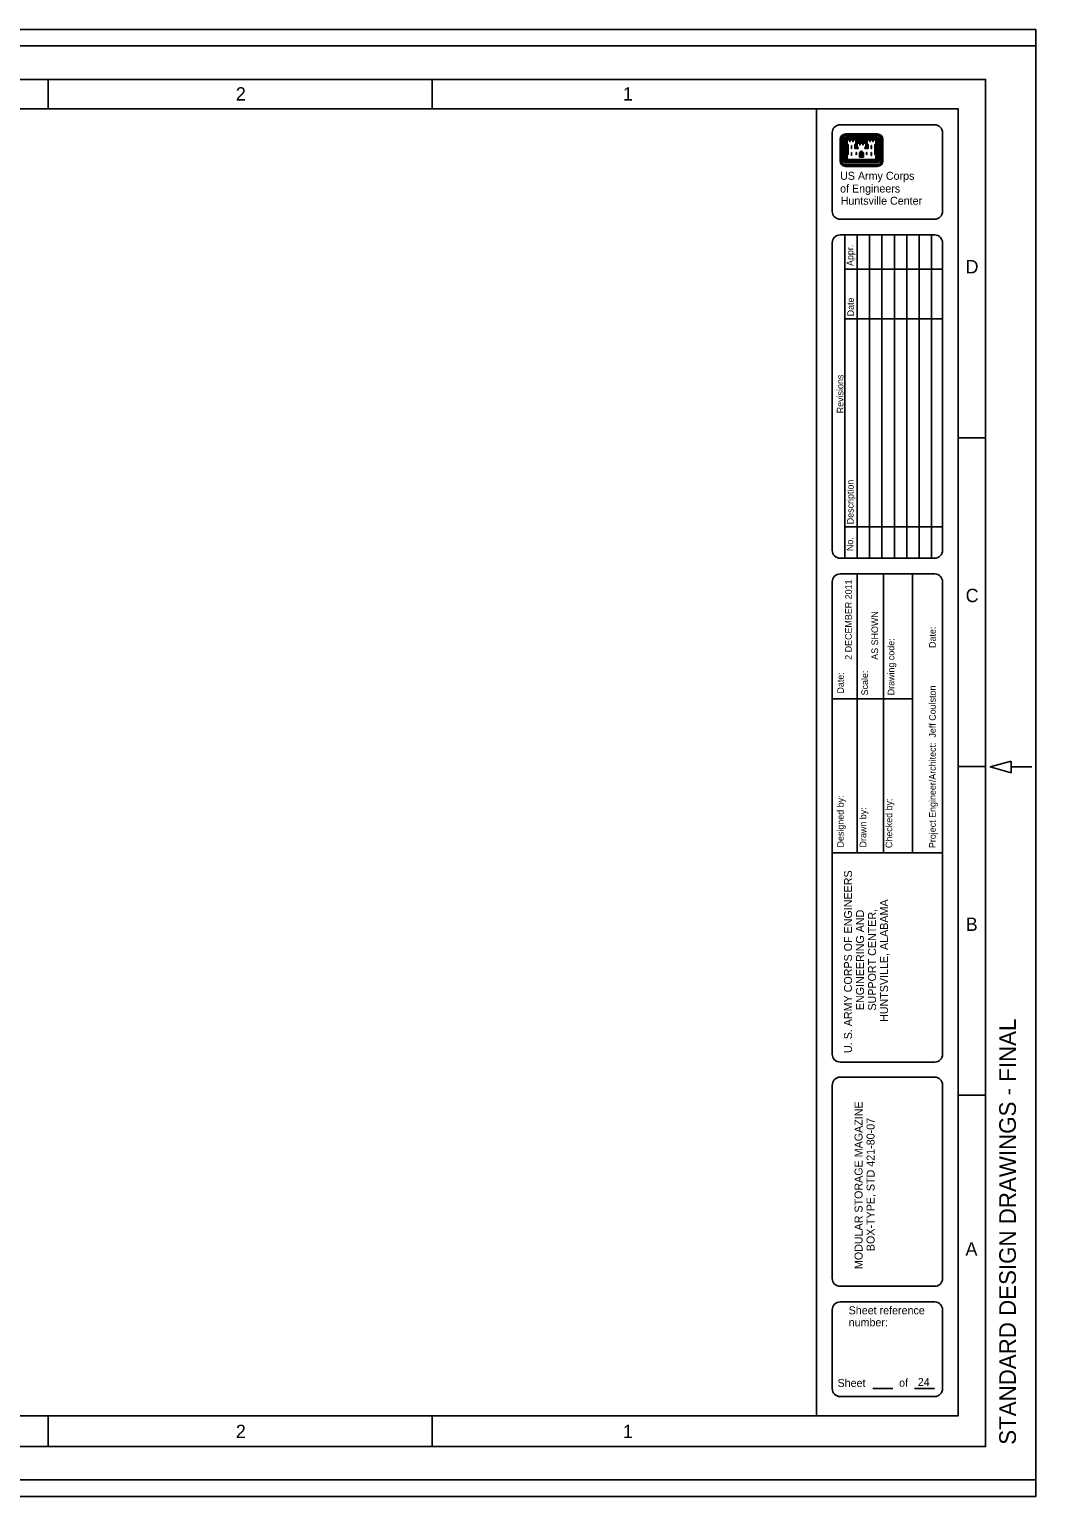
# Model space of a CAD drawing. Extents: x -0.04 to 2.79, y -0.02 to 1.81.
# Drawn here: x 1.534 to 2.792, y -0.021 to 1.813 of the extents above; entities that cross this region are included whole.
import ezdxf

# ---------------------------------------------------------------- set-up
doc = ezdxf.new("R2010")
doc.units = 0
for name, color, linetype in [('G-ANNO-NPLT', 7, 'Continuous'), ('G-ANNO-PLOT', 7, 'Continuous'), ('G-ANNO-TTLB', 7, 'Continuous')]:
    doc.layers.add(name, color=color, linetype=linetype)

msp = doc.modelspace()

# ---------------------------------------------------------------- linework, layer by layer
at = {"layer": 'G-ANNO-NPLT'}
msp.add_lwpolyline([(-0.0417, 1.8125), (2.7917, 1.8125), (2.7917, -0.0208), (-0.0417, -0.0208)], close=True, dxfattribs=at)
at = {"layer": 'G-ANNO-PLOT'}
for p, q in [((2.7917, 1.8125), (-0.0417, 1.8125)), ((2.7917, 1.8125), (2.7917, -0.0208)), ((2.7917, -0.0208), (-0.0417, -0.0208))]:
    msp.add_line(p, q, dxfattribs=at)
msp.add_lwpolyline([(0, 0), (2.7917, 0), (2.7917, 1.7917), (0, 1.7917)], close=True, dxfattribs=at)
at = {"layer": 'G-ANNO-TTLB'}
for p, q in [((1.5578, 1.7131), (1.5578, 1.75)), ((2.0378, 1.7131), (2.0378, 1.75)), ((2.5178, 0.0803), (2.5178, 1.7131)), ((2.5473, 1.6749), (2.5473, 1.6483)), ((2.5477, 1.6749), (2.5477, 1.6483)), ((2.5484, 1.6749), (2.5484, 1.6483)), ((2.5489, 1.6749), (2.5489, 1.6483)), ((2.5494, 1.6749), (2.5494, 1.6483)), ((2.5517, 1.6749), (2.5517, 1.6483)), ((2.5523, 1.6749), (2.5523, 1.6483)), ((2.5528, 1.6749), (2.5528, 1.6483)), ((2.5534, 1.6749), (2.5534, 1.6483)), ((2.554, 1.6749), (2.554, 1.6483)), ((2.5938, 1.6819), (2.5543, 1.6819)), ((2.5938, 1.6815), (2.5543, 1.6815)), ((2.5938, 1.6809), (2.5543, 1.6809)), ((2.5938, 1.6804), (2.5543, 1.6804)), ((2.5938, 1.6798), (2.5543, 1.6798)), ((2.5938, 1.6776), (2.5543, 1.6776)), ((2.5938, 1.677), (2.5543, 1.677)), ((2.5938, 1.6764), (2.5543, 1.6764)), ((2.5938, 1.6758), (2.5543, 1.6758)), ((2.5938, 1.6753), (2.5543, 1.6753)), ((2.5545, 1.6749), (2.5545, 1.6484)), ((2.5551, 1.6749), (2.5551, 1.649)), ((2.5555, 1.6692), (2.5555, 1.6556)), ((2.5561, 1.6686), (2.5561, 1.6563)), ((2.5679, 1.6747), (2.5801, 1.6747)), ((2.5679, 1.6742), (2.5801, 1.6742)), ((2.5679, 1.6737), (2.5801, 1.6737)), ((2.5679, 1.6731), (2.5801, 1.6731)), ((2.5679, 1.6725), (2.5801, 1.6725)), ((2.5679, 1.672), (2.5801, 1.672)), ((2.5679, 1.6714), (2.5801, 1.6714)), ((2.592, 1.6686), (2.592, 1.6563)), ((2.5925, 1.6692), (2.5925, 1.6557)), ((2.593, 1.6749), (2.593, 1.649)), ((2.5935, 1.6749), (2.5935, 1.6484)), ((2.5941, 1.6749), (2.5941, 1.6483)), ((2.5947, 1.6749), (2.5947, 1.6483)), ((2.5953, 1.6749), (2.5953, 1.6483)), ((2.5958, 1.6749), (2.5958, 1.6483)), ((2.5964, 1.6749), (2.5964, 1.6483)), ((2.5986, 1.6749), (2.5986, 1.6483)), ((2.5992, 1.6749), (2.5992, 1.6483)), ((2.5997, 1.6749), (2.5997, 1.6483)), ((2.6003, 1.6749), (2.6003, 1.6483)), ((2.6007, 1.6749), (2.6007, 1.6483)), ((2.5714, 1.6528), (2.5714, 1.6572)), ((2.5714, 1.6528), (2.5767, 1.6528)), ((2.5719, 1.6528), (2.5719, 1.6572)), ((2.5725, 1.6528), (2.5725, 1.6572)), ((2.5731, 1.6528), (2.5731, 1.6572)), ((2.5737, 1.6528), (2.5737, 1.6572)), ((2.5744, 1.6528), (2.5744, 1.6572)), ((2.575, 1.6528), (2.575, 1.6572)), ((2.5755, 1.6528), (2.5755, 1.6572)), ((2.5761, 1.6528), (2.5761, 1.6572)), ((2.5767, 1.6528), (2.5767, 1.6572)), ((2.5938, 1.6478), (2.5543, 1.6478)), ((2.5938, 1.6473), (2.5543, 1.6473)), ((2.5938, 1.6467), (2.5543, 1.6467)), ((2.5938, 1.6462), (2.5543, 1.6462)), ((2.5938, 1.6456), (2.5543, 1.6456)), ((2.5938, 1.6433), (2.5543, 1.6433)), ((2.5938, 1.6428), (2.5543, 1.6428)), ((2.5938, 1.6423), (2.5543, 1.6423)), ((2.5938, 1.6417), (2.5543, 1.6417)), ((2.5938, 1.6412), (2.5543, 1.6412)), ((2.5935, 1.6484), (2.5545, 1.6484)), ((2.593, 1.649), (2.5551, 1.649)), ((2.5532, 1.5557), (2.5532, 1.1517)), ((2.5686, 1.5557), (2.5686, 1.1517)), ((2.5842, 1.5557), (2.5842, 1.1517)), ((2.5996, 1.5557), (2.5996, 1.1517)), ((2.6151, 1.5557), (2.6151, 1.1517)), ((2.6306, 1.5557), (2.6306, 1.1517)), ((2.646, 1.5557), (2.646, 1.1517)), ((2.6615, 1.5557), (2.6615, 1.1517)), ((2.5532, 1.513), (2.6754, 1.513)), ((2.5532, 1.4507), (2.6754, 1.4507)), ((2.695, 1.3022), (2.7292, 1.3022)), ((2.5532, 1.1911), (2.6754, 1.1911)), ((2.5685, 1.1321), (2.5685, 0.976)), ((2.6014, 1.1321), (2.6014, 0.976)), ((2.6377, 1.1321), (2.6377, 0.7837)), ((2.6377, 0.976), (2.5376, 0.976)), ((2.5685, 0.976), (2.5685, 0.7837)), ((2.6014, 0.976), (2.6014, 0.7837)), ((2.695, 0.8914), (2.7292, 0.8914)), ((2.7609, 0.891), (2.787, 0.891)), ((2.6754, 0.7837), (2.5376, 0.7837)), ((2.5474, 0.5221), (2.6655, 0.5221)), ((2.695, 0.4806), (2.7292, 0.4806)), ((2.5883, 0.1141), (2.6134, 0.1141)), ((2.6403, 0.1141), (2.6654, 0.1141)), ((1.5578, 0.0418), (1.5578, 0.0803)), ((2.0378, 0.0418), (2.0378, 0.0803))]:
    msp.add_line(p, q, dxfattribs=at)
for points in [[(0.0833, 0.0417), (2.7292, 0.0417), (2.7292, 1.75), (0.2515, 1.75)], [(0.1166, 0.0803), (2.695, 0.0803), (2.695, 1.7131), (0.1166, 1.7131)], [(2.5474, 1.6934), (2.6655, 1.6934)], [(2.5376, 1.5851), (2.5376, 1.6835)], [(2.5555, 1.6749), (2.5555, 1.6698), (2.5567, 1.6686), (2.5567, 1.6563), (2.5555, 1.6551), (2.5555, 1.6494), (2.5926, 1.6494), (2.5926, 1.6551), (2.5914, 1.6563), (2.5914, 1.6686), (2.5926, 1.6698), (2.5926, 1.6749), (2.5877, 1.6749), (2.5839, 1.6749), (2.5804, 1.6749), (2.5804, 1.6698), (2.5817, 1.6686), (2.5817, 1.6642), (2.5789, 1.6642), (2.5789, 1.6646), (2.5801, 1.6657), (2.5801, 1.6708), (2.5752, 1.6708), (2.5714, 1.6708), (2.5679, 1.6708), (2.5679, 1.6657), (2.5691, 1.6646), (2.5691, 1.6642), (2.5664, 1.6642), (2.5664, 1.6686), (2.5676, 1.6698), (2.5676, 1.6749), (2.5626, 1.6749), (2.5589, 1.6749), (2.5555, 1.6749)], [(2.5561, 1.6743), (2.5561, 1.67), (2.5573, 1.6688), (2.5573, 1.656), (2.5561, 1.6549), (2.5561, 1.65), (2.592, 1.65), (2.592, 1.6549), (2.5909, 1.656), (2.5909, 1.6688), (2.592, 1.67), (2.592, 1.6743), (2.5886, 1.6743), (2.5886, 1.6723), (2.5883, 1.6723), (2.5883, 1.6743), (2.5848, 1.6743), (2.5848, 1.6723), (2.5845, 1.6723), (2.5845, 1.6743), (2.581, 1.6743), (2.581, 1.67), (2.5822, 1.6688), (2.5822, 1.6636), (2.5784, 1.6636), (2.5784, 1.6648), (2.5796, 1.6659), (2.5796, 1.6703), (2.5761, 1.6703), (2.5761, 1.6682), (2.5757, 1.6682), (2.5757, 1.6703), (2.5723, 1.6703), (2.5723, 1.6682), (2.5719, 1.6682), (2.5719, 1.6703), (2.5685, 1.6703), (2.5685, 1.6659), (2.5697, 1.6648), (2.5697, 1.6636), (2.5658, 1.6636), (2.5658, 1.6688), (2.5671, 1.67), (2.5671, 1.6743), (2.5636, 1.6743), (2.5636, 1.6723), (2.5633, 1.6723), (2.5633, 1.6743), (2.5598, 1.6743), (2.5598, 1.6723), (2.5595, 1.6723), (2.5595, 1.6743), (2.5561, 1.6743)], [(2.5673, 1.6687), (2.567, 1.6684), (2.567, 1.6647), (2.5682, 1.6647), (2.5674, 1.6655), (2.5674, 1.6688)], [(2.5807, 1.6687), (2.581, 1.6684), (2.581, 1.6647), (2.5799, 1.6647), (2.5807, 1.6655), (2.5807, 1.6688)], [(2.6754, 1.6835), (2.6754, 1.5851)], [(2.5614, 1.6674), (2.5614, 1.6636), (2.5617, 1.6636), (2.5617, 1.6674), (2.5614, 1.6674)], [(2.5614, 1.6587), (2.5614, 1.6549), (2.5617, 1.6549), (2.5617, 1.6587), (2.5614, 1.6587)], [(2.5673, 1.6587), (2.5673, 1.6561), (2.5677, 1.6561), (2.5677, 1.6587), (2.5673, 1.6587)], [(2.5807, 1.6587), (2.5807, 1.6561), (2.5804, 1.6561), (2.5804, 1.6587), (2.5807, 1.6587)], [(2.5867, 1.6674), (2.5867, 1.6636), (2.5863, 1.6636), (2.5863, 1.6674), (2.5867, 1.6674)], [(2.5867, 1.6587), (2.5867, 1.6549), (2.5863, 1.6549), (2.5863, 1.6587), (2.5867, 1.6587)], [(2.6655, 1.5753), (2.5474, 1.5753)], [(2.5376, 1.5458), (2.5376, 1.1615)], [(2.6655, 1.5557), (2.5474, 1.5557)], [(2.6754, 1.1615), (2.6754, 1.5458)], [(2.5474, 1.1517), (2.6655, 1.1517)], [(2.5376, 1.1223), (2.5376, 0.5321)], [(2.6655, 1.1321), (2.5474, 1.1321)], [(2.6754, 0.5319), (2.6754, 1.1223)], [(2.6655, 0.5033), (2.5474, 0.5033)], [(2.5376, 0.493), (2.5376, 0.2518)], [(2.6754, 0.2518), (2.6754, 0.4935)], [(2.5474, 0.242), (2.6655, 0.242)], [(2.5474, 0.2224), (2.6655, 0.2224)], [(2.5376, 0.1141), (2.5376, 0.2126)], [(2.6754, 0.2126), (2.6754, 0.1141)], [(2.6655, 0.1043), (2.5474, 0.1043)]]:
    msp.add_lwpolyline(points, dxfattribs=at)
msp.add_lwpolyline([(2.7609, 0.8983), (2.735, 0.891), (2.7609, 0.8837)], close=True, dxfattribs=at)
for centre, major_axis, start_param, end_param in [((2.5474, 1.6835), (-0.00984, 0), 4.712389, 6.283185), ((2.6655, 1.6835), (-0.00984, 0), 3.141593, 4.712389), ((2.5543, 1.6749), (-0.00696, 0), 4.712389, 6.283185), ((2.5543, 1.6749), (-0.00656, 0), 4.712389, 6.283185), ((2.5543, 1.6749), (-0.006, 0), 4.712389, 6.283185), ((2.5543, 1.6749), (-0.00543, 0), 4.712389, 6.283185), ((2.5543, 1.6749), (-0.00487, 0), 4.712389, 6.283185), ((2.5543, 1.6749), (-0.00261, 0), 4.712389, 6.283185), ((2.5543, 1.6749), (-0.00205, 0), 4.712389, 6.283185), ((2.5543, 1.6749), (-0.00148, 0), 4.712389, 6.283185), ((2.5543, 1.6749), (0.000919, 0), 1.570796, 3.141593), ((2.5543, 1.6749), (-0.000355, 0), 4.712389, 6.283185), ((2.5938, 1.6749), (-0.00696, 0), 3.141593, 4.712389), ((2.5938, 1.6749), (0.00656, 0), 0, 1.570796), ((2.5938, 1.6749), (0.006, 0), 0, 1.570796), ((2.5938, 1.6749), (0.00543, 0), 0, 1.570796), ((2.5938, 1.6749), (0.00487, 0), 0, 1.570796), ((2.5938, 1.6749), (-0.00261, 0), 3.141593, 4.712389), ((2.5938, 1.6749), (-0.00205, 0), 3.141593, 4.712389), ((2.5938, 1.6749), (-0.00148, 0), 3.141593, 4.712389), ((2.5938, 1.6749), (-0.000919, 0), 3.141593, 4.712389), ((2.5938, 1.6749), (-0.000355, 0), 3.141593, 4.712389), ((2.575, 1.6569), (0.00361, 0), 1.844255, 3.072783), ((2.575, 1.6569), (-0.00304, 0), 4.947481, 6.214375), ((2.575, 1.6569), (-0.00248, 0), 4.947481, 6.214375), ((2.575, 1.6569), (-0.00192, 0), 4.947481, 6.214375), ((2.5731, 1.6569), (0.00135, 0), 0.06881, 1.335704), ((2.5731, 1.6569), (0.00192, 0), 0.06881, 1.335704), ((2.5731, 1.6569), (-0.00248, 0), 3.210403, 4.477297), ((2.575, 1.6569), (-0.00135, 0), 4.947481, 6.214375), ((2.5731, 1.6569), (0.00304, 0), 0.06881, 1.335704), ((2.5731, 1.6569), (0.00361, 0), 0.06881, 1.298435), ((2.5543, 1.6482), (0.00696, 0), 3.141593, 4.712389), ((2.5543, 1.6482), (0.00656, 0), 3.141593, 4.712389), ((2.5543, 1.6482), (-0.006, 0), 0, 1.570796), ((2.5543, 1.6482), (0.00543, 0), 3.141593, 4.712389), ((2.5543, 1.6482), (0.00487, 0), 3.141593, 4.712389), ((2.5543, 1.6482), (0.00261, 0), 3.141593, 4.712389), ((2.5543, 1.6482), (0.00205, 0), 3.141593, 4.712389), ((2.5543, 1.6482), (0.00148, 0), 3.141593, 4.712389), ((2.5543, 1.6482), (0.000919, 0), 3.141593, 4.712389), ((2.5543, 1.6482), (0.000355, 0), 3.141593, 4.712389), ((2.5938, 1.6482), (0.00696, 0), 4.712389, 6.283185), ((2.5938, 1.6482), (0.00261, 0), 4.712389, 6.283185), ((2.5938, 1.6482), (0.00205, 0), 4.712389, 6.283185), ((2.5938, 1.6482), (0.00148, 0), 4.712389, 6.283185), ((2.5938, 1.6482), (0.000919, 0), 4.712389, 6.283185), ((2.5938, 1.6482), (0.000355, 0), 4.712389, 6.283185), ((2.5938, 1.6482), (0.00487, 0), 4.712389, 6.283185), ((2.5938, 1.6482), (0.00543, 0), 4.712389, 6.283185), ((2.5938, 1.6482), (0.006, 0), 4.712389, 6.283185), ((2.5938, 1.6482), (0.00656, 0), 4.712389, 6.283185), ((2.5474, 1.5851), (-0.00984, 0), 0, 1.570796), ((2.6655, 1.5851), (0.00984, 0), 4.712389, 6.283185), ((2.5474, 1.5458), (-0.00984, 0), 4.712389, 6.281588), ((2.6655, 1.5458), (-0.00984, 0), 3.141593, 4.712389), ((2.5474, 1.1615), (-0.00984, 0), 0, 1.570796), ((2.6655, 1.1615), (0.00984, 0), 4.712389, 6.283185), ((2.5474, 1.1223), (-0.00984, 0), 4.712389, 6.283185), ((2.6655, 1.1223), (-0.00984, 0), 3.141593, 4.712389), ((2.5474, 0.5319), (-0.00984, 0), 6.267222, 7.853982), ((2.6655, 0.5319), (0.00984, 0), 4.712389, 6.283185), ((2.5474, 0.4935), (-0.00984, 0), 4.712389, 6.327939), ((2.6655, 0.4935), (0.00984, 0), 0, 1.570796), ((2.5474, 0.2518), (-0.00984, 0), 0, 1.570796), ((2.6655, 0.2518), (0.00984, 0), 4.712389, 6.283185), ((2.5474, 0.2126), (-0.00984, 0), 4.712389, 6.283185), ((2.6655, 0.2126), (0.00984, 0), 0, 1.570796), ((2.5474, 0.1141), (-0.00984, 0), 0, 1.570796), ((2.6655, 0.1141), (0.00984, 0), 4.712389, 6.283185)]:
    msp.add_ellipse(centre, major_axis=major_axis, ratio=0.999936, start_param=start_param, end_param=end_param, dxfattribs=at)

# ---------------------------------------------------------------- texts
for s, height, p in [('2', 0.0167, (1.7923, 1.7235)), ('1', 0.0167, (2.2759, 1.7235)), ('US Army Corps', 0.01, (2.5473, 1.6245)), ('of Engineers', 0.01, (2.5473, 1.6086)), ('Huntsville Center', 0.01, (2.548, 1.5934)), ('D', 0.0167, (2.7041, 1.5076)), ('D', 0.0167, (2.7041, 1.5076)), ('C', 0.0167, (2.7042, 1.0968)), ('B', 0.0167, (2.7043, 0.686)), ('A', 0.0167, (2.704, 0.2804)), ('Sheet reference', 0.01, (2.558, 0.207)), ('number:', 0.01, (2.558, 0.192)), ('Sheet', 0.01, (2.5441, 0.1162)), ('of', 0.01, (2.621, 0.1165)), ('24', 0.01, (2.6444, 0.1174)), ('2', 0.0167, (1.7923, 0.0523)), ('1', 0.0167, (2.2759, 0.0523))]:
    msp.add_text(s, height=height, dxfattribs=at).set_placement(p)
for s, height, p in [('Appr.', 0.00833, (2.5639, 1.5168)), ('Date', 0.00833, (2.5646, 1.4539)), ('Revisions', 0.00833, (2.5515, 1.3328)), ('Description', 0.008333, (2.5642, 1.1941)), ('No.', 0.00833, (2.5637, 1.1606)), ('2 DECEMBER 2011', 0.008333, (2.5619, 1.0248)), ('AS SHOWN', 0.00833, (2.5948, 1.0248)), ('Date:', 0.00833, (2.6669, 1.0396)), ('Drawing code:', 0.008333, (2.6151, 0.9804)), ('Scale:', 0.00833, (2.5822, 0.9803)), ('Date:', 0.00833, (2.552, 0.9826)), ('Project Engineer/Architect:  Jeff Coulston', 0.008333, (2.6669, 0.7895)), ('Designed by:', 0.008333, (2.5519, 0.7903)), ('Checked by:', 0.008333, (2.6125, 0.7895)), ('Drawn by:', 0.00833, (2.5801, 0.7903)), ('U. S. ARMY CORPS OF ENGINEERS', 0.01, (2.5622, 0.5335)), ('HUNTSVILLE, ALABAMA', 0.01, (2.6072, 0.5723)), ('ENGINEERING AND', 0.01, (2.5772, 0.587)), ('SUPPORT CENTER,', 0.01, (2.5922, 0.5865)), ('STANDARD DESIGN DRAWINGS - FINAL', 0.020833, (2.767, 0.044)), ('MODULAR STORAGE MAGAZINE', 0.01, (2.5754, 0.2635)), ('BOX-TYPE, STD 421-80-07', 0.01, (2.5904, 0.2859))]:
    msp.add_text(s, height=height, rotation=90, dxfattribs=at).set_placement(p)

doc.saveas('drawing.dxf')
